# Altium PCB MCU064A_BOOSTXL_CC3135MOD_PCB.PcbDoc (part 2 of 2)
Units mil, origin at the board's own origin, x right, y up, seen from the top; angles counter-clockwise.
Board outline 2300 x 1700 mil, 2 copper layers (Top Layer, Bottom Layer), stack 45.707 mil thick; 110 components, 81 nets, 379 pads, 305 vias.
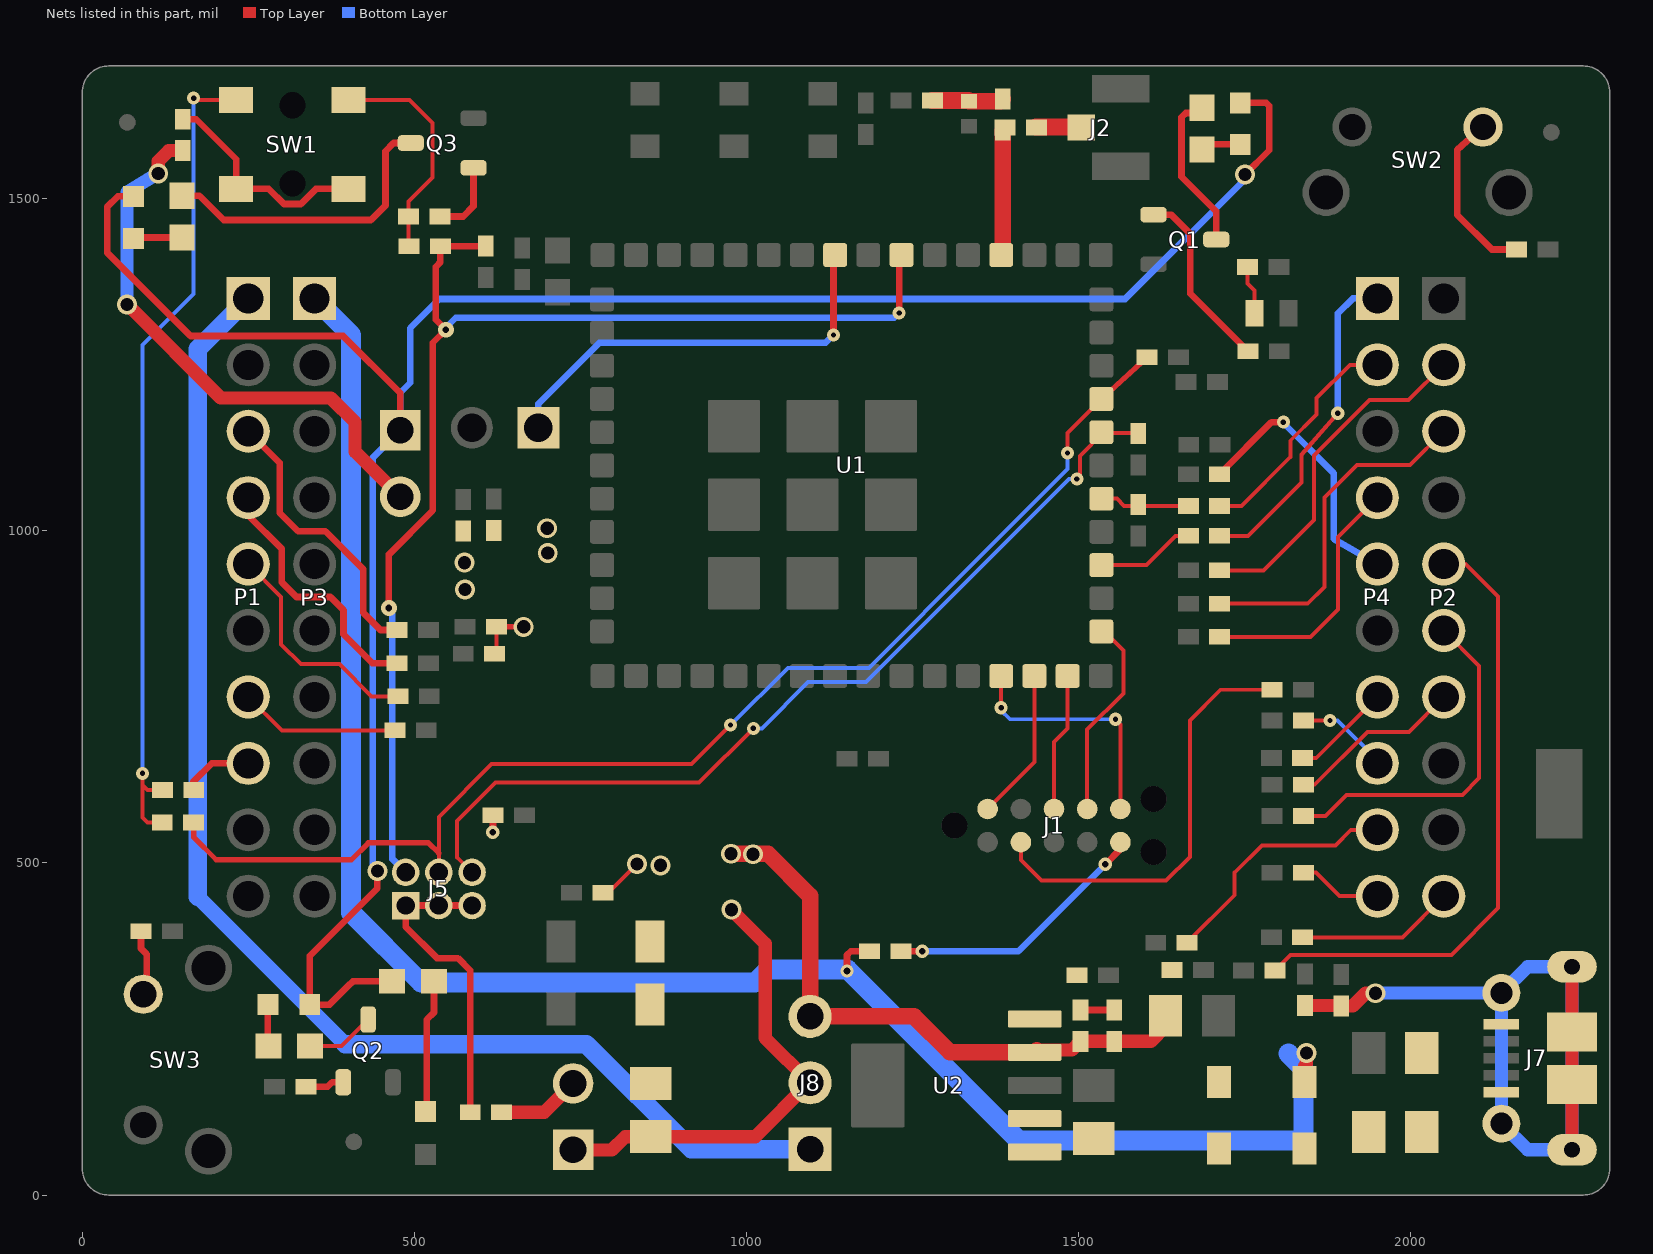
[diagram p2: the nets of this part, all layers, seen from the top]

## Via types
v1: diameter 19.68, hole 7.87, Top Layer to Bottom Layer, tented both sides, 240 vias
v2: diameter 19.68, hole 7.87, Top Layer to Bottom Layer, 40 vias
v3: diameter 30, hole 20, Top Layer to Bottom Layer, tented both sides, 19 vias
v4: diameter 20, hole 10, Top Layer to Bottom Layer, tented both sides, 4 vias
v5: diameter 24, hole 10, Top Layer to Bottom Layer, tented both sides, 2 vias

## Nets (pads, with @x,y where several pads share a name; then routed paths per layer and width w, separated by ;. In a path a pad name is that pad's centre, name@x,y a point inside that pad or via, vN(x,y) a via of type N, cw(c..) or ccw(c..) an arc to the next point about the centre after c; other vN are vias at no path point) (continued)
NetC4_1: C4.1 J2.1 | length 68
  Top Layer w25: J2.1@1502.86,1608.3 J2.1@1503.86,1607.3
  Top Layer w25.4: C4.1@1436.32,1608.3 J2.1@1502.86,1608.3
NetC5_2: C5.2 C7.2 L1.1 | length 107.7
  Top Layer w25.4: C7.2@1280.24,1647.9 1334.3,1647.9 L1.1@1335.3,1646.9 1382.4,1646.9 C5.2@1386,1650.5
NetC8_2: C8.2 R36.1 R37.2 U2.5 | length 51
  Top Layer w10: R36.1@1503,278.62 C8.2@1554,278.62
NetC14_1: C14.1 J7.6 J7.7 J7.8 J7.9 J7.10 J7.11 R38.1 | length 1295.1
  Top Layer w20: R38.1@1841,285.38 C14.1@1893.87,285.38 ; C14.1@1895.8,284.68 1912.98,284.68 1932.2,303.9 v3(1947.2,303.9) ; J7.6@2243.08,68.2 J7.7@2243.08,166.63 J7.8@2243.08,245.37 J7.9@2243.08,343.8
  Bottom Layer w20: v3(1947.2,303.9) J7.10@2136.78,304.43 ; J7.10@2136.78,304.43 2176.15,343.8 J7.9@2243.08,343.8 J7.6@2243.08,68.2 2176.15,68.2 J7.11@2136.78,107.57 J7.10@2136.78,304.43
NetD1_1: D1.1 R44.2 | length 57.2
  Top Layer w10: R44.2@1685.9,1581.98 D1.1@1743.13,1581.98
NetD2_1: D2.1 R41.1 | length 73.9
  Top Layer w6: R41.1@1754.76,1397.3 1754.76,1372.34 1764.92,1362.18 D2.1@1764.92,1327.6
NetD4_2: D4.2 L4.2
NetD5_2: D5.2 R42.1 | length 201.2
  Top Layer w10: D5.2@516.6,125.98 518.8,128.18 518.8,264.1 529.6,274.9 R42.1@529.6,321.8
NetD6_1: D6.1 R45.2 | length 62.8
  Top Layer w10: D6.1@279.6,286.8 279.6,224.88 R45.2@280.25,224.23
NetD7_1: D7.1 R40.2 | length 73.3
  Top Layer w10: D7.1@77.5,1440.5 78.7,1441.7 R40.2@150.3,1441.7
NetJ1_2: J1.2 R1.1 | length 657.2
  Top Layer w6: J1.2@1413.2,531.3 1413.2,504.7 1444.4,473.5 1631.9,473.5 1667.7,509.3 1667.7,714.8 1713.7,760.8 R1.1@1791.48,760.8
NetJ1_5: J1.5 R2.2 | length 404.1
  Top Layer w10: R2.2@1232.62,367.2 v4(1264.9,367.2) ; v4(1540.3,497.9) 1563.2,520.8 J1.5@1563.2,530.7
  Bottom Layer w10: v4(1264.9,367.2) 1409.6,367.2 v4(1540.3,497.9)
NetJ4_1: J4.1 U1.36 | length 649.2
  Top Layer w10: v1(1131.2,1295.1) 1131.2,1416.33 U1.36@1134.3,1419.43
  Bottom Layer w10: J4.1@686.8,1155.2 686.8,1191.37 778.63,1283.2 1119.3,1283.2 v1(1131.2,1295.1)
NetJ5_1: J5.1 J5.3 J5.5 R7.2 | length 469.7
  Top Layer w10: R7.2@584.28,124.9 584.28,205.72 584.28,236.12 584.28,338.22 565.7,356.8 534.2,356.8 487,404 J5.1@487,435.9 J5.3@537,435.9 J5.5@587,435.9
NetJ5_2: J5.2 R8.1 R13.1 U1.34 | length 1850.9
  Top Layer w10: v5(461.8,883.9) 461.8,964.7 527.9,1030.8 527.9,1283.2 v5(547.5,1302.8) 532.2,1318.1 532.2,1397.56 539.32,1404.68 R8.1@539.32,1428.6 539.44,1428.72 R13.1@607.7,1428.72 ; v1(1230.1,1328.2) 1230.1,1413.43 U1.34@1233.8,1417.13
  Bottom Layer w10: v5(461.8,883.9) 467,873.67 467,505.9 J5.2@487,485.9 ; v5(547.5,1302.8) 547.5,1305.96 562.34,1320.8 1222.7,1320.8 v1(1230.1,1328.2)
NetJ5_4: J5.4 R9.1 R12.1 U1.24 | length 1903.5
  Top Layer w6: J5.4@537,485.9 537,569.4 616.6,649 917.5,649 v1(976.3,707.8) ; v1(1483.5,1117.3) 1483.5,1147.42 U1.24@1534.58,1198.5
  Top Layer w8: R9.1@167.82,561 167.82,538.88 201.9,504.8 405.3,504.8 430.8,530.3 521.5,530.3 537,514.8 ; U1.24@1534.58,1198.5 U1.24@1538.96,1202.5 ; U1.24@1535.28,1202.5 U1.24@1538.96,1202.5 ; U1.24@1544,1202.5 U1.24@1538.96,1202.5 ; R12.1@1603.18,1261.2 U1.24@1538.96,1202.5
  Bottom Layer w6: v1@972.2,703.7 v1(976.3,707.8) 1062.4,793.9 1184.38,793.9 1351.18,960.69 1351.32,960.69 1483.5,1092.87 v1(1483.5,1117.3)
NetJ5_6: J5.6 R11.1 U1.23 | length 1376.3
  Top Layer w6: J5.6@581.6,491.3 J5.6@587,485.9 564.3,508.6 564.3,563.2 622.3,621.2 929,621.2 v1(1010.5,702.7) ; v1(1497.5,1078.1) 1502.34,1082.94 1502.34,1112.94 1537.9,1148.5 U1.23@1534.58,1148.5 ; U1.23@1538.8,1147.6 R11.1@1583.82,1147.6
  Bottom Layer w6: v1(1010.5,702.7) 1023.3,702.7 1093,772.4 1180,772.4 1485.7,1078.1 v1(1497.5,1078.1)
NetJ7_1: J7.1 L4.1
NetJ7_5: J7.5 L5.2
NetP1_3: P1.3 R20.2 | length 438.4
  Top Layer w10: P1.3@257.6,1150 P1.3@250,1150 297.3,1102.7 297.3,1027.2 325.1,999.4 366.1,999.4 423.4,942.1 423.4,876.6 449.2,850.8 R20.2@474.28,850.8
NetP1_4: P1.4 R22.2 | length 393.8
  Top Layer w10: P1.4@250,1050 250,1023.4 300.6,972.8 300.6,922.5 322.6,900.5 373.7,900.5 393.48,880.72 393.48,844.42 437.1,800.8 R22.2@474.28,800.8
NetP1_5: P1.5 R25.2 | length 349.5
  Top Layer w6: P1.5@250,950 299.6,900.4 299.6,829.28 329.58,799.3 387.2,799.3 435.7,750.8 R25.2@475.28,750.8
NetP1_7: P1.7 R29.2 | length 241.4
  Top Layer w6: P1.7@250,750 300.7,699.3 R29.2@470.38,699.3
NetP1_8: P1.8 R31.2 | length 107
  Top Layer w10: R31.2@168,610 167,611 167,621.9 195.1,650 P1.8@250,650
NetP2_2: P2.2 R18.1 | length 522.4
  Top Layer w6: R18.1@1712.62,940.5 1778.6,940.5 1854.3,1016.2 1854.3,1113.2 1938.1,1197 1997,1197 P2.2@2050,1250
NetP2_3: P2.3 R19.1 | length 523.7
  Top Layer w6: R19.1@1712.62,890.5 1845.2,890.5 1870.3,915.6 1870.3,1050.2 1919.6,1099.5 1999.5,1099.5 P2.3@2050,1150
NetP2_5: P2.5 R24.1 | length 946.5
  Top Layer w6: R24.1@1795.62,338 1819.32,361.7 2061.6,361.7 2131.9,432 2131.9,901.1 2083,950 P2.5@2050,950
NetP2_6: P2.6 R26.1 | length 534.3
  Top Layer w6: R26.1@1837.1,570.7 1872.1,570.7 1903.9,602.5 2078.2,602.5 2103.4,627.7 2103.4,796.6 P2.6@2050,850
NetP2_7: P2.7 R28.1 | length 267
  Top Layer w6: R28.1@1837.71,617.8 1855.3,617.8 1934.9,697.4 1997.4,697.4 P2.7@2050,750
NetP2_10: P2.10 R34.1 | length 238.1
  Top Layer w6: R34.1@1837.62,388 1988,388 P2.10@2050,450
NetP4_1: P4.1 R16.2 | length 500.4
  Top Layer w6: R16.2@1712.62,992.5 1755.5,992.5 1835.5,1072.5 1835.5,1114.12 v1(1890.4,1177.1)
  Bottom Layer w10: v1(1890.4,1177.1) 1890.4,1327.3 1913.1,1350 P4.1@1950,1350
NetP4_2: P4.2 R17.2 | length 354.3
  Top Layer w6: R17.2@1712.62,1037.5 1745.5,1037.5 1818.9,1110.9 1818.9,1135.7 1858.65,1175.45 1858.65,1200.05 1908.6,1250 P4.2@1950,1250
NetP4_4: P4.4 R21.2 | length 388.1
  Top Layer w6: R21.2@1712.62,840.5 1849.7,840.5 1890.6,881.4 1890.6,990.6 P4.4@1950,1050
NetP4_5: P4.5 R23.2 | length 413.7
  Top Layer w10: R23.2@1712.62,1085.5 1790.82,1163.7 v1(1808.5,1163.7)
  Bottom Layer w10: v1@1806.1,1165 1884.1,1087 1884.1,987.98 P4.5@1950,950
NetP4_7: P4.7 R27.2 | length 150.5
  Top Layer w6: R27.2@1837.62,658 1858,658 P4.7@1950,750
NetP4_8: P4.8 R30.2 | length 153.9
  Top Layer w6: R30.2@1838.72,714.5 v1(1878.8,714.5)
  Top Layer w10: P4.8@1950,636.9 P4.8@1950,650
  Bottom Layer w6: v1(1878.8,714.5) 1890.3,714.5 1950,654.8 P4.8@1950,650
NetP4_9: P4.9 R32.2 | length 376.6
  Top Layer w6: R32.2@1663.62,380 1735.3,451.68 1735.3,485.5 1776.3,526.5 1887,526.5 1910.5,550 P4.9@1950,550
NetP4_10: P4.10 R33.2 | length 125.9
  Top Layer w6: R33.2@1838.72,485.4 1857.8,485.4 1893.2,450 P4.10@1950,450
NetQ1_1: Q1.1 R46.2 | length 280
  Top Layer w10: Q1.1@1612.96,1476.1 1639.3,1476.1 1668.5,1446.9 1668.5,1356.98 R46.2@1755.08,1270.4
NetQ1_3: Q1.3 R44.1 | length 239
  Top Layer w10: R44.1@1685.9,1629.22 1661.72,1629.22 1655.2,1622.7 1655.2,1533.3 1707.44,1481.06 Q1.3@1707.44,1438.7
NetQ2_1: Q2.1 R47.2 | length 59.1
  Top Layer w10: R47.2@336.82,163 369.5,163 376.36,169.86 Q2.1@393.1,169.86
NetQ2_3: Q2.3 R45.1 | length 103.9
  Top Layer w6: R45.1@343.25,224.23 390.39,224.23 Q2.3@430.5,264.34
NetQ3_1: Q3.1 R43.2 | length 114.6
  Top Layer w10: R43.2@538.72,1473.4 573.7,1473.4 589.24,1488.94 Q3.1@589.24,1546.6
NetQ3_3: Q3.3 R40.1 | length 455.6
  Top Layer w10: R40.1@150.3,1504.7 176.4,1504.7 213.1,1468 434.7,1468 456.6,1489.9 456.6,1571.7 468.9,1584 Q3.3@494.76,1584
NetR39_1: R39.1 SW1.1 SW1.2 | length 338.2
  Top Layer w10: R39.1@151.4,1619.82 171.68,1619.82 231.85,1559.65 SW1.1@231.85,1514.97 280.98,1514.97 303.79,1492.16 329.21,1492.16 352.02,1514.97 SW1.2@401.15,1514.97
NetR48_2: R48.2 SW3.1 | length 100.5
  Top Layer w10: R48.2@88.58,397.2 88.58,371.12 96.99,362.71 96.99,307.42 SW3.1@91.86,302.29
NetR49_2: R49.2 SW2.1 | length 260.9
  Top Layer w10: SW2.1@2108.97,1607.91 2070.1,1573.8 2070.1,1476 2122.44,1423.66 R49.2@2159.83,1423.66
RF_BG: C4.2 C5.1 U1.31 | length 184.9
  Top Layer w6: U1.31@1383.88,1419.85 U1.31@1383.94,1419.92
  Top Layer w10: U1.31@1383.88,1419.85 U1.31@1384.3,1419.43
  Top Layer w25.4: U1.31@1383.94,1419.92 1386,1421.97 C5.1@1386,1603.25
SFL_CLK: J1.8 U1.15 | length 208.7
  Top Layer w6: J1.8@1463.2,581.3 1463.2,682.1 1483.6,702.5 U1.15@1483.6,781.57
SFL_CS: J1.10 U1.14 | length 230.4
  Top Layer w6: J1.10@1363.2,581.3 1433.6,651.7 U1.14@1433.6,781.57
  Top Layer w10: U1.14@1433.6,781.57 U1.14@1434.3,780.87
SFL_MISO: J1.6 U1.13 | length 370.3
  Top Layer w6: v1(1383.6,733.7) U1.13@1383.6,781.57 ; v1(1555.6,716.4) 1563.2,708.8 J1.6@1563.2,581.3
  Top Layer w10: J1.6@1563.2,580.7 J1.6@1563.2,581.3
  Bottom Layer w6: v1(1383.6,733.7) 1383.6,729.9 1397.1,716.4 v1(1555.6,716.4)
  Bottom Layer w10: v1@1381.7,734.3 1382.3,733.7 v1(1383.6,733.7)
SFL_MOSI: J1.7 U1.17 | length 311.9
  Top Layer w6: J1.7@1513.2,581.3 1513.2,700.8 1567.7,755.3 1567.7,820.08 1539.28,848.5 U1.17@1534.58,848.5
  Top Layer w10: U1.17@1535.28,852.5 U1.17@1539.28,848.5
SOP_00: R8.2 R43.1 SW1.3 | length 341.3
  Top Layer w6: SW1.3@401.15,1648.83 492.77,1648.83 527.4,1614.2 527.4,1532 507,1511.6 491.48,1496.08 R43.1@491.48,1473.4 491.48,1429.2 R8.2@492.08,1428.6
SOP_01: R9.2 R31.1 SW1.4 | length 1247.8
  Top Layer w6: v1(90.8,635) 90.8,617.8 ; R9.2@120.58,561 98.1,561 90.8,568.3 90.8,617.8 ; R31.1@120.76,610 98.6,610 90.8,617.8 ; v1@167.77,1648.83 SW1.4@231.85,1648.83 ; v1@167.8,1648.86 v1(167.8,1651.5)
  Bottom Layer w6: v1(90.8,635) 90.8,1279.7 167.8,1356.7 v1(167.8,1651.5)
TEST_29: R16.1 U1.19 | length 149
  Top Layer w6: U1.19@1534.58,948.5 1602.3,948.5 1646.3,992.5 R16.1@1665.38,992.5
TEST_30: R14.2 R17.1 U1.21 | length 140.2
  Top Layer w6: U1.21@1534.58,1048.5 1557.86,1048.5 1568.86,1037.5 R14.2@1592.8,1037.5 ; R14.2@1589.4,1040.9 R14.2@1592.8,1037.5 ; R17.1@1665.38,1037.5 R14.2@1592.8,1037.5
VBAT_CC: C1.1 C11.1 C12.1 J6.2 L2.2 R5.1 R6.1 R7.1 R35.2 | length 287.9
  Top Layer w6: R6.1@620.92,814.9 623.62,817.6 R5.1@623.62,855.7 ; v3@664.7,845 v3(664.7,855.6) ; C1.1@783.82,455.3 792.1,455.3 v3(835.3,498.5)
  Top Layer w8: R5.1@623.62,855.7 655.4,855.7 655.5,855.6 v3(664.7,855.6)
  Top Layer w10: C11.1@845.09,382 C11.1@845.6,382.51
  Top Layer w20: R7.1@632.72,124.7 695.7,124.7 J6.2@739,168
  other v3: 870.8,496.4 576.2,911.8 575.5,952.1
VCC_BRD: J3.2 J6.1 J8.2 R15.2 R35.1 R39.2 | length 1588
  Top Layer w6: v4(618,546.1) v4@618.58,546.68 ; R15.2@618,571.12 R15.2@618.58,571.7
  Top Layer w10: v4@618.58,546.68 R15.2@618.58,571.7
  Top Layer w20: v3(67.5,1341) 208.4,1200.1 374.4,1200.1 410.8,1163.7 410.8,1119.3 J3.2@478.8,1051.3 ; v3(114.5,1538.2) 114.5,1556.6 130.48,1572.58 R39.2@151.4,1572.58 ; J6.1@739,68 797.7,68 817.7,88 R35.1@856,88 1013.27,88 1094.27,169 J8.2@1096,169 1028.6,236.4 1028.6,378.6 v3(977.5,429.7)
  Bottom Layer w20: v3(67.5,1341) 67.5,1509.9 v3(114.5,1538.2) ; v3@974.54,433.11 v3@981.46,426.22
VCC_BRD_5V: C13.1 D3.1 D4.1 U2.1 U2.2
VCC_LDO_3V3: C8.1 C9.1 C10.1 J8.3 L3.2 R36.2 U2.4 | length 917
  Top Layer w20: U2.4@1437.41,218.3 1489.92,218.3 R36.2@1503,231.38 C8.1@1554,231.38 1609.28,231.38 1631,253.1 C9.1@1631,270
  Top Layer w25: v3(976.8,513.9) 1032.5,513.9 1096,450.4 J8.3@1096,269 1252.5,269 1306.5,215 U2.4@1434.11,215 U2.4@1437.41,218.3
  other v3: 1010,513.1 701,966.7 700.1,1004
VCC_LED: D1.2 D6.2 D7.2 J3.1 R42.2 | length 3455.1
  Top Layer w6: D6.2@342.6,286.8 D6.2@342.6,293.03
  Top Layer w10: D7.2@77.5,1503.5 77.4,1503.6 53.6,1503.6 37.6,1487.6 37.6,1419.1 163.22,1293.48 392.82,1293.48 478.8,1207.5 J3.1@478.8,1151.3 ; v3(444.5,488) 444.5,461.9 342.6,360 D6.2@342.6,286.8 372.5,286.8 401.1,315.4 407.5,321.8 R42.2@466.6,321.8 ; D1.2@1743.6,1644.5 1782.6,1644.5 1787.2,1639.9 1787.2,1573.2 v3(1750.7,1536.7)
  Bottom Layer w10: v3(444.5,488) 440.4,488 437.29,491.11 437.29,1109.79 J3.1@478.8,1151.3 478.8,1208 493.9,1223.1 493.9,1305.3 537.64,1349.04 1570.27,1349.04 1750.7,1529.48 v3(1750.7,1536.7)
VCC_MCU_3V3: J8.1 P1.1 | length 2011.9
  Bottom Layer w23: 173.9,449.2 395.9,227.2
  Bottom Layer w28: 173.9,449.2 173.9,1273.9 P1.1@250,1350 ; 395.9,227.2 759.1,227.2 917.3,69 J8.1@1096,69
VCC_MCU_5V: D3.2 P3.1 R2.1 | length 2782.4
  Top Layer w10: v4(1151.4,337.3) 1151.4,361.51 1157.09,367.2 R2.1@1185.38,367.2
  Top Layer w19.68: D3.2@1840.47,170 1840.47,194.43 1843.4,197.36 v3(1843.4,213.9)
  Bottom Layer w30: P3.1@350,1350 405,1295 405,425 510,320 1013.13,320 1032.93,339.8 1152.27,339.8 1410.07,82 1832.6,82 1838.6,88 1838.6,190.4 1816,213
pads on no net: E1.3 E1.4 E1.5 E1.6 FID1.1 FID2.1 FID3.1 FID4.1 FID5.1 FID6.1 J1.3 J1.4 J1.MH1 J1.MH2 J1.MH3 J2.2@1563.9,1666.36 J2.3@1563.9,1548.24 J7.2 J7.3 J7.4 P1.2 P1.6 P1.9 P1.10 P2.4 P2.8 P2.9 P3.3 P3.4 P3.5 P3.6 P3.7 P3.8 P3.9 P3.10 P4.3 P4.6 SW1.MH1 SW1.MH2 SW2.MH1 SW2.MH2 SW3.MH1 SW3.MH2 U1.3 U1.9 U1.10 U1.12 U1.18 U1.20 U1.22 U1.33 U1.39 U1.41 U1.42 U1.45 U1.53 U1.54 U1.55@1003.09,899.68 U1.55@1003.09,942.99 U1.56@1077.89,899.68 U1.56@1077.89,942.99 U1.56@1121.2,899.68 U1.56@1121.2,942.99 U1.57@1196,899.68 U1.57@1196,942.99 U1.57@1239.31,899.68 U1.57@1239.31,942.99 U1.58@959.78,1017.79 U1.58@959.78,1061.1 U1.58@1003.09,1017.79 U1.58@1003.09,1061.1 U1.59@1077.89,1017.79 U1.59@1077.89,1061.1 U1.59@1121.2,1017.79 U1.59@1121.2,1061.1 U1.60@1196,1017.79 U1.60@1196,1061.1 U1.60@1239.31,1017.79 U1.60@1239.31,1061.1 U1.61@959.78,1135.9 U1.61@959.78,1179.21 U1.61@1003.09,1135.9 U1.61@1003.09,1179.21 U1.62@1077.89,1135.9 U1.62@1077.89,1179.21 U1.62@1121.2,1135.9 U1.62@1121.2,1179.21 U1.63@1196,1135.9 U1.63@1196,1179.21 U1.63@1239.31,1135.9 U1.63@1239.31,1179.21 U2.6@1175.84,135.28 U2.6@1175.84,194.72 U2.6@1219.94,135.28 U2.6@1219.94,194.72

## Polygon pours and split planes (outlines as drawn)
GND on Top Layer "GND_L01_P121" (solid, remove dead copper, pour order 121): -10,1658.1 -10,1675.5 11.7,1697.2 2268,1697.2 2268,1692.7 2285.3,1675.4 2289.7,1671 2289.7,19.1 2289.7,1.7 2281,-7 2276.6,-2.6 11.7,-2.6 -10,19.1
NetC2_1 on Top Layer "NETC2_1_L01_P096" (solid, remove dead copper, pour order 96): 644.33,1395.7 739.78,1395.7 761.9,1395.7 771.2,1386.4 704.46,1293.04 661.2,1219.67 649.13,1199.2 649.13,1186.07 642.55,1038.15 633.7,1029.3 545.7,1029.3 544,1219.67
VBAT_CC on Top Layer "VBAT_CC_L01_P094" (solid, remove dead copper, pour order 94): 602.79,1024.17 532.87,1024.17 532.5,1023.8 529.5,1020.8 529.51,914.29 529.51,889.3 598.1,889.3 603.5,894.7 602.79,959.8
VCC_LDO_3V3 on Top Layer "VCC_LDO_3V3_L01_P092" (solid, remove dead copper, pour order 92): 602.79,1022.29 730.38,1022.3 730.38,960.02 710.25,939.7 602.6,939.7
VBAT_CC on Top Layer "TOP-GND" (solid, remove dead copper, pour order 38): 701.94,231 743,231 763.7,241.9 763.7,469.4 815.2,520.9 884.2,520.9 940.9,464.2 940.9,166.8 894.88,120.77 711.13,120.77 680.17,151.73 680.17,209.23
GND on Top Layer "Top Layer-GND" (solid, remove dead copper, pour order 33): 1690,235 1770,235 1821.87,235 1821.87,315 1690,315 1685,310 1685,238 1687,236 1688,235 1691,235
VCC_LDO_3V3 on Top Layer "Top Layer-VCC_LDO_3V3" (solid, remove dead copper, pour order 36): 1382,225 1382,205 1387,200 1482,200 1492,210 1562,210 1577,225 1657,225 1662,230 1662,345 1652,355 1577,355 1572,350 1572,255 1567,250 1492,250 1486,244 1477,235 1459,235 1387,235 1382,230 1382,224
NetC8_2 on Top Layer "Top Layer-NetC29_2" (solid, remove dead copper, pour order 35): 1388.46,251.82 1478.11,251.82 1483.68,257.39 1486.48,260.19 1494.84,260.19 1561.19,260.19 1565,264 1565,298 1559,304 1522,304 1516.31,309.69 1513.88,312.12 1513.88,333.1 1513.88,347.85 1511.81,349.92 1409.58,349.92 1394.94,335.28 1384.38,324.72 1384.38,273.35 1384.38,254.74 1386.97,252.15
GND on Top Layer "TOP-GND" (solid, pour order 34): 428 vertices, not listed, extent 1927.21,1050.03 2099,1419
VCC_BRD_5V on Top Layer "TOP-VCC_BRD_5V" (solid, pour order 37): 1376,55 1376,125 1386,135 1478,135 1488.01,125 1567.99,124.99 1592,149 1592,186.8 1610.2,205 1721.66,205 1738.46,188.2 1738.46,39.08 1719.38,20 1596,20 1571,45 1386,45
NetJ7_1 on Top Layer "Top Layer-NetJ7_1" (solid, remove dead copper, pour order 31): 1989.09,64.08 1989.09,128.09 2025,164 2026,165 2053,165 2162.3,165 2163.65,163.65 2163.65,146.44 2162.21,145 2087.51,145 2074.27,131.75 2074.27,60.27 2067,53 2000.17,53
NetJ7_5 on Top Layer "Top Layer-NetJ7_5" (solid, remove dead copper, pour order 30): 1991.25,246.86 2014.39,270 2159.31,270 2164.38,264.92 2164.38,249.41 2162.12,247.14 2099.9,247.14 2076.57,223.81 2076.57,185.57 2064,173 2001.29,173 1991.25,183.04
NetD4_2 on Top Layer "Top Layer-NetD4_2" (solid, remove dead copper, pour order 32): 1821.43,45.07 1827.52,38.99 1946.16,38.99 1963.54,56.37 1963.54,126.33 1958.88,130.99 1901.5,130.99 1894.5,123.99 1869.5,98.99 1856.5,98.99 1825.76,98.99 1821.43,94.66
GND on Bottom Layer "GND_L02_P100" (solid, remove dead copper, pour order 100): -1.1,1661.9 21.4,1684.4 21.4,1691.8 2250.5,1691.8 2272.9,1714.2 2299,1688.1 2299,1676.8 2299,38.8 2302.8,35 2276.6,8.8 2276.6,-9.9 13.9,-9.9 6.4,-17.4 -12.3,1.3 -12.3,20
VBAT_CC on Bottom Layer "VBAT_CC_L02_P084" (solid, remove dead copper, pour order 84): 667.9,986.9 556.1,983.4 584.8,752.98 592.94,656.98 797.1,470.9 895.5,470.9 895.5,500.6 728.1,699.6 690.5,875 674.87,947.89
VCC_LDO_3V3 on Bottom Layer "VCC_LDO_3V3_L02_P082" (solid, remove dead copper, pour order 82): 915.65,500.96 732.3,684.31 674.6,959.2 670.4,1034.1 671.72,1035.42 730.2,1035.42 730.2,1034.1 732.3,1032 783.6,973.57 792.5,700.3 892.3,612.2 1073.3,495.2
VCC_LED on Bottom Layer "Bottom Layer-No Net 2" (solid, remove dead copper, pour order 64): 517.2,1107.1 425.4,1107.1 406.3,1126.2 419.9,1309.45 486.85,1309.45 516.5,1288.3 517.2,1287.6
VCC_MCU_5V on Bottom Layer "Bottom Layer-No Net" (solid, remove dead copper, pour order 58): 1246.02,245.05 1907.71,236.06 1936,147 1900.04,58.4 1619.9,58.4 1327.56,58.4
VCC_MCU_3V3 on Bottom Layer "Bottom Layer-No Net 1" (solid, remove dead copper, pour order 60): 778.1,33.9 1136.8,33.9 1136.8,99.9 1037.3,99.9 947.9,142.2 778.1,235.94
VCC_BRD on Bottom Layer "Bottom Layer-No Net 3" (solid, remove dead copper, pour order 66): 449,1080.6 565.13,1080.6 623.21,624.44 648.48,606.92 794.4,461 996,461 996,430 996,418.6 945.4,418.6 836.8,418.6 758.8,418.6 477.85,517.85 447,1080
no net on Keep-Out Layer "Keep-Out Layer-No Net" (solid, remove dead copper): 812,1693.1 812,1631.4 812.6,1630.8 794.1,1630.8 794.1,1619.7 792.5,1618.1 795.1,1615.5 896,1615.5 896,1693.1
no net on Keep-Out Layer "Keep-Out Layer-No Net" (solid, remove dead copper): 793,1489.8 794,1490.8 1024.4,1490.8 1024.4,1629.7 1021.7,1632.4 1021.2,1632.9 896,1632.9 896,1619.2 896,1615.5 899.7,1615.5 792.5,1615.5

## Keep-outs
Top Layer:
  circle w0: c1872.75,1509.49 r45
  circle w0: c2148.34,1509.49 r45
  circle w0: c190.28,341.66 r45
  circle w0: c190.28,66.07 r45
Bottom Layer:
  circle w0: c316.5,1522.84 r23
  circle w0: c316.5,1640.96 r23
  circle w0: c190.28,66.07 r45
  circle w0: c1872.55,1509.38 r45
  circle w0: c2148.44,1509.88 r45
  circle w0: c190.28,341.66 r45
Keep-Out Layer:
  lines w10: 10,1700 2260,1700 cw(c2260,1660) 2300,1660 2300,40 cw(c2260,40) 2260,0 40,0 cw(c40,40) 0,40 0,1660 cw(c40,1660) 40,1700
  text ".Layer_Name" at 727,-858.49 h60

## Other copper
Top Layer:
  pour cut-out: 1168,1612.4
  pour cut-out: 1168.1,1665.8 1249.3,1665.8 1274.5,1665.8 1273,1628.1 1258.3,1628.1 1191.9,1628.1 1191.9,1613.4 1190.1,1611.6 1168.1,1612.4
  pour cut-out: 787.98,1688.6 1168,1688.6 1168,1495.8 1074,1495.8 788.3,1495.8
  pour cut-out: 367.1,808.2 367.1,818.04 393.48,844.42 448.4,789.5 546.2,789.5 546.2,750.8 435.7,750.8
  pour cut-out: 808.47,115.38 820.81,127.71 912.74,127.71 912.74,105.13 902.65,95.04 828.01,95.04 808.15,114.9
  pour cut-out: 2197.55,96.93 2197.55,302.63 2204.97,310.05 2258.54,310.05 2267.53,301.06 2267.53,102.43 2252.67,87.57 2207.99,87.57 2197.52,98.04
  pour cut-out: 287,1313 213,1313 213,1387 287,1387
  pour cut-out: 1859,259 1857,261 1857,264 1862,269 1912,269 1915,266 1915,260 1914,259
  pour cut-out: 1474.94,1574.69 1474.78,1639.6 1532.44,1639.6 1532.54,1574.85
  pour cut-out: 1352.12,1350.59 1352.12,1442.9 1414.08,1442.9 1414.08,1350.67
  text "L01 TOP LAYER" at 727,-858.49 h60
Bottom Layer:
  pour cut-out: 787.98,1688.6 1167.98,1688.6 1167.98,1508.6 1073.98,1508.6 788.28,1508.6
  text "L04 BOTTOM LAYER" at 727,-858.49 h60

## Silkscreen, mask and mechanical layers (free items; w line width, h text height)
Top Overlay:
  drawing of 2694 lines, arcs and shapes, not listed
  text "FRST" at 88.2,1658.9 h30
  text "BOOSTXL-CC3135MOD" at 860.3,1482 h45
  text "RST" at 1730.4,1451.5 h32
  text "P4" at 1929,1417 h30
  text "P2" at 2025,1417 h30
  text "P3" at 329,1393.6 h30
  text "P1" at 189,1392.3 h30
  text "IRQ" at 2121.4,1231.7 h30
  text "VCC_RST" at 594.3,1227.2 h40
  text "CS#" at 2115.1,1145.2 h30
  text "TX" at 130.4,1130.5 h30
  text "RX" at 130.1,1034.6 h30
  text "CTS" at 1826.1,1009.7 h30
  text "RTS" at 1828.9,938.1 h30
  text "RST" at 2122.9,933.5 h30
  text "nHIB" at 77.9,931.1 h30
  text "VCC_LED" at 439.4,900.2 h72.83
  text "MOSI" at 2120.3,838 h30
  text "MISO" at 2086.7,735.7 h30
  text "CLK" at 98.3,735.1 h30
  text "NWP" at 1902,708 h30 r90
  text "FRST" at 77.1,640.3 h30
  text "MAC" at 1905,598 h30 r90
  text "RST*" at 2122.5,436.7 h30
  text "LDO" at 1158,258 h32
  text "VBAT_CC" at 573.8,181.2 h32
  text "PWR" at 558.3,166.3 h30 r90
  text "nHIB" at 243.8,94.2 h30
  text "VCC_BRD" at 570.1,49.6 h32
  text "MCU" at 1156,47 h32
  text "USB PWR" at 1930.68,13.61 h30
  text ".Layer_Name" at 727,-858.49 h60
Bottom Overlay:
  drawing of 3506 lines, arcs and shapes, not listed
  text "For evaluation only;  / not FCC approved for resale." at 1824.3,1476.1 h60
  text "P1" at 286.4,1430.2 h32
  text "1" at 200.4,1425.03 h40
  text "P4" at 2006.17,1421.63 h32
  text "P2" at 2094.71,1422.25 h32
  text "21" at 485.7,1420.4 h40
  text "5V" at 547.6,1342.9 h72.83
  text "40" at 1876.6,1339.9 h40
  text "GND" at 2282.8,1333.1 h72.83
  text "3V3" at 148.9,1326.7 h72.83
  text "GND" at 581.9,1237.4 h72.83
  text "IRQ" at 2207.9,1207.54 h30
  text "TX" at 196.4,1108.1 h30
  text "CS#" at 2214.49,1108.31 h30
  text "CTS" at 1866,1037.8 h30
  text "RX" at 196.4,1009.7 h30
  text "RTS" at 1896,913.88 h30
  text "RST" at 2214.97,910.31 h30
  text "nHIB" at 196.4,906.5 h30
  text "SimpleLink BoosterPack" at 1672.8,825.9 h72.83
  text "MOSI" at 2228.11,809.21 h30
  text "BOOSTXL-CC3135MOD" at 1672.8,768.8 h72.83
  text "NWP" at 1866,732.9 h30
  text "MISO" at 2238.74,707.71 h30
  text "CLK" at 196.4,706.18 h30
  text "FRST" at 196.4,608.18 h30
  text "MAC" at 1896,597.18 h30
  text "RST*" at 2225,410.81 h30
  text "10" at 284.5,336.1 h40
  text "30" at 396.6,318.48 h40
  text "11" at 2091.55,316.83 h40
  text "31" at 1988.55,314.41 h40
  text "Rev A" at 1784.8,207 h40
  text "MCU064" at 1813.9,77.66 h50
  text ".Layer_Name" at 727,-858.49 h60
  text "String" at 1998.3,-1110.9 h72.83
Top Paste:
  text ".Layer_Name" at 727,-858.49 h60
Bottom Paste:
  text ".Layer_Name" at 727,-858.49 h60
Top Solder:
  text ".Layer_Name" at 727,-858.49 h60
  text ".Layer_Name" at 727,-858.49 h60
Bottom Solder:
  text ".Layer_Name" at 727,-858.49 h60
Drill Guide:
  text ".Layer_Name" at 727,-858.49 h60
M1 Board Outline:
  the board outline again, w10
M2 Board Dimensions:
  rectangle: 150,-275 275,-150
  rectangle: 275,-400 650,-275
  lines w1: 2208.99,1759 2210,1760
  lines w7: 150,-275 1150,-275 ; 275,-400 275,-150 ; 400,-400 400,-150 ; 650,-400 650,-150 ; 900,-400 900,-150 ; 150,-400 1150,-400 1150,-150 150,-150 150,-400
  lines w10: -77.03,0.12 -0.85,0.12 ; -19.29,-18.32 -0.85,0.12 ; -19.29,18.57 -0.85,0.12 ; 2291.28,1726.64 2291.28,1691.28 ; 2326.64,1691.28 2291.28,1691.28 ; 2361.99,1762 2291.28,1691.28 ; 2363,1763 2548,1763
  text "R" at 2568,1753 h25
  text "40.00 mil X4" at 2608,1753 h25
  text "(0,0)" at -125.16,-57.16 h25
M3 3D STEP Top:
  text ".Layer_Name" at 727,-858.49 h60
M4 3D STEP Bottom:
  text ".Layer_Name" at 727,-858.49 h60
M5 Assembly Top:
  circle w6: c460.4,344.8 r8
  circle w6: c626.8,1546.6 r8
  circle w6: c1434.88,31.28 r8
  circle w6: c1170.94,24.1 r8
  circle w6: c668.69,24.35 r8
  circle w6: c2088.18,154.32 r8
  rectangle: 1777.62,1664.6 1838.88,1676.98
  rectangle: 199.95,1413.88 217.3,1474.9
  lines w10: -142,-930.17 6458,-930.17 ; -142,-726.83 6460,-726.83 ; -142,-523.5 -142,-1133.5 3863,-1133.5 6460,-1133.5 6460,-523.5 -141.5,-523.5 -141.5,-1133.5 1434,-1133.5 ; 2323,-1133.5 2323,-523.5 ; 3590,-726.83 3590,-523.5 ; 4430,-726.83 4430,-523.5 ; 5052,-1140 5052,-937.17
  text "COMPONENTS MARKED 'DNP' SHOULD NOT BE POPULATED." at 1303.5,-318.5 h60
  text "ASSEMBLY VARIANT:" at 1303,-434 h60
  text ".VariantName" at 2339,-434 h60
  text ".PRJ_Number" at 2863.59,-655.43 h60
  text "PCB VIEWED FROM TOP SIDE" at -78.5,-655.67 h60
  text "BOARD #:" at 2398,-655.67 h60
  text "REV:" at 3788,-655.67 h60
  text ".PCB_Rev" at 4079.5,-655.67 h60
  text "SVN REV:" at 4626,-655.67 h60
  text ".VersionControl_RevNumber" at 5132,-655.67 h60
  text ".Layer_Name" at 741.3,-859.5 h60
  text ".plot_File_Name" at 595.7,-1062.9 h60
  text "PLOT NAME =" at -78.5,-1064.33 h60
  text "GENERATED    :" at 2400,-1064.33 h60
  text ".Print_Date" at 3269.5,-1064.33 h60
  text ".Print_Time" at 3998.5,-1064.33 h60
  text "TEXAS INSTRUMENTS" at 5263,-1064.33 h60
M6 Assembly Bottom:
  lines w10: -142.5,-727.33 6459.5,-727.33 ; -140.5,-930.67 6459.5,-930.67 ; 1265.5,-1140.5 1265.5,-937.67 ; 1887.5,-727.33 1887.5,-524 ; 2727.5,-727.33 2727.5,-524 ; 3994.5,-1134 3994.5,-524 ; 4883.5,-1134 6459,-1134 6459,-524 -142.5,-524 -142.5,-1134 2454.5,-1134 6459.5,-1134 6459.5,-524
  text "COMPONENTS MARKED 'DNP' SHOULD NOT BE POPULATED." at 6252,-318 h60
  text ".VariantName" at 5208,-434 h60
  text "ASSEMBLY VARIANT:" at 6247,-434 h60
  text ".VersionControl_RevNumber" at 1185.5,-656.17 h60
  text "SVN REV:" at 1691.5,-656.17 h60
  text ".PCB_Rev" at 2238,-656.17 h60
  text "REV:" at 2529.5,-656.17 h60
  text ".PRJ_Number" at 3374,-656.17 h60
  text "BOARD #:" at 3919.5,-656.17 h60
  text "PCB VIEWED FROM BOTTOM SIDE" at 6396,-656.17 h60
  text ".Layer_Name" at 731.6,-852.6 h60
  text ".plot_File_Name" at 5736,-1059.7 h60
  text "TEXAS INSTRUMENTS" at 1054.5,-1064.83 h60
  text ".Print_Time" at 2319,-1064.83 h60
  text ".Print_Date" at 3048,-1064.83 h60
  text "GENERATED    :" at 3917.5,-1064.83 h60
  text "PLOT NAME =" at 6396,-1064.83 h60
M9 Title Sheet:
  drawing of 57 lines, arcs and shapes, not listed
  text "1" at 889.84,8036.5 h70
  text "2" at 3385.5,8036.5 h70
  text "3" at 5874.84,8036.5 h70
  text "4" at 8381.51,8036.5 h70
  text "5" at 10880.5,8036.5 h70
  text "6" at 13385.5,8036.5 h70
  text "A" at -266.5,6893.5 h70
  text "A" at 14533.5,6893.5 h70
  text "B" at -266.5,4513.5 h70
  text "B" at 14533.5,4513.5 h70
  text "C" at -266.5,2138.5 h70
  text "C" at 14533.5,2138.5 h70
  text "PROJECT TITLE:" at 11493.5,277.5 h45
  text ".PRJ_Title" at 11543.5,144.17 h70
  text "DESIGNED FOR:" at 11493.5,-23.5 h45
  text ".PRJ_Customer" at 11543.5,-163.5 h70
  text "D" at -266.5,-231.5 h70
  text "D" at 14533.5,-231.5 h70
  text "FILE NAME:" at 11493.5,-323.5 h45
  text ".PCB_File_Name_No_Path" at 11543.5,-443.5 h70
  text "Texas Instruments (TI) and/or its licensors do not warrant the accuracy or completeness of this specification" at 6524,-605.34 h45
  text "ENGINEER:" at 11493.5,-613.5 h45
  text "LAYOUT BY:" at 12998.5,-613.5 h45
  text "or any information contained therein. TI and/or its licensors do not warrant that this design will meet" at 6479.01,-718 h45
  text ".PRJ_Engineer" at 11543.5,-768.49 h70
  text ".PCB_Layout" at 13049,-768.49 h70
  text "the specifications, will be suitable for your application or fit for any particular purpose, or will operate in" at 6479.01,-830.67 h45
  text "ALTIUM DESIGNER VERSION:" at 12998.5,-923.5 h45
  text "an implementation. TI and/or its licensors do not warrant that the design is production worthy. You should" at 6479.01,-943.33 h45
  text "completely validate and test your design implementation to confirm the system functionality for your application." at 6524,-1056 h45
  text ".print_Scale" at 11543.5,-1056.83 h70
  text ".Application_BuildNumber" at 13049,-1056.83 h70
  text "1" at 889.84,-1263.5 h70
  text "2" at 3385.5,-1263.5 h70
  text "3" at 5874.84,-1263.5 h70
  text "4" at 8381.51,-1263.5 h70
  text "5" at 10880.5,-1263.5 h70
  text "6" at 13385.5,-1263.5 h70
M10 Fab Notes:
  drawing of 185 lines, arcs and shapes, not listed
  text "DESIGN INFORMATION" at 12531.02,5910 h60
  text "MIN. TRACK WIDTH:" at 11886.46,5730 h60
  text "6" at 12982.7,5730 h60
  text "MIL" at 13137.46,5730 h60
  text "3" at 12985,5600 h60
  text "MIN. CLEARANCE:" at 11886.46,5598 h60
  text "MIL" at 13137.46,5598 h60
  text "MIN. VIA PAD SIZE:" at 11886.46,5466 h60
  text "MIL" at 13137.46,5466 h60
  text "0.05mm (2MIL)" at 12581.46,5324.29 h60
  text "MINIMUM ANNULAR RING" at 11557.23,5320.01 h60
  text "EXTERNAL" at 13289.46,5320.01 h60
  text "PER" at 11757.23,5202 h60
  text "IPC-D-275 CLASS 2 LEVEL C" at 11977.23,5202 h60
  text "MIL, HOLES" at 13465.46,5089.71 h60
  text "+/-" at 13073,5089 h60
  text "+/-" at 13927,5089 h60
  text "REGISTRATION TOLERANCES:" at 11557.23,5084 h60
  text "METAL" at 12757,5084 h60
  text "5" at 13333.2,5084 h60
  text "3" at 14166.2,5084 h60
  text "MIL" at 14282.46,5084 h60
  text "MATERIAL:" at 11482.46,4874.54 h60
  text "FR-4 High Tg" at 12468.9,4734.21 h60
  text "FR-408" at 11903.46,4725.64 h60
  text "X" at 12315.46,4725.64 h60
  text "OTHER" at 13391.46,4725.64 h60
  text "1.2 mm+/-10%" at 13755,4565 h60
  text "62 MIL (1.6mm) +/-10%" at 12223.56,4562.92 h60
  text "THICKNESS:" at 11557.23,4558.64 h60
  text "X" at 13390.4,4558.64 h60
  text "OTHER" at 13488.46,4558.64 h60
  text "TOLERANCE:" at 11557.23,4400.64 h60
  text "X" at 12396.53,4400.64 h60
  text "ANSI IPC-6012 TYPE 3 CLASS 2" at 12583.48,4400.64 h60
  text "OTHER +/-" at 12583.46,4244.64 h60
  text "BOW & TWIST:" at 11557.23,4087.64 h60
  text "X" at 12396.53,4087.64 h60
  text "ANSI IPC-6012 TYPE 3 CLASS 2" at 12583.48,4087.64 h60
  text "OTHER +/-" at 12583.46,3929.13 h60
  text "DRILLING:" at 11482.46,3790.64 h60
  text "REFERENCE:" at 11557.23,3673.64 h60
  text "X" at 12205.46,3673.64 h60
  text "AS SHOWN" at 12392.46,3673.64 h60
  text "X" at 13106.46,3673.64 h60
  text "NC_DRILL FILES" at 13243.46,3673.64 h60
  text "PTH MIN COPPER THICKNESS:" at 11557.23,3515.64 h60
  text "X" at 12907.46,3515.64 h60
  text "1MIL" at 13044.46,3515.64 h60
  text "OTHER" at 13541.46,3515.64 h60
  text "BOARD FINISH:" at 11482.46,3356.64 h60
  text "SILKSCREEN:" at 11637.68,3238.64 h60
  text "X" at 12586.46,3238.64 h60
  text "TOP" at 12712.46,3238.64 h60
  text "X" at 13096.46,3238.64 h60
  text "BOTTOM" at 13223.46,3238.64 h60
  text "SILKSCREEN COLOR:" at 11637.68,3071.64 h60
  text "X" at 12585.42,3071.64 h60
  text "WHITE" at 12712.46,3071.64 h60
  text "OTHER" at 13223.46,3071.64 h60
  text "SOLDER RESIST COLOR:" at 11637.68,2901.64 h60
  text "X" at 13310.42,2747.44 h60
  text "GREEN" at 12332.46,2742.44 h60
  text "BLUE" at 12923.46,2742.44 h60
  text "OTHER" at 13461.46,2742.44 h60
  text "RED" at 13851.46,2737.44 h60
  text "IMMERSION GOLD (ENIG)" at 12543.46,2553.92 h60
  text "ENEPIG" at 13881,2550.64 h60
  text "SURFACE FINISH:" at 11482.46,2549.64 h60
  text "X" at 12356.51,2549.64 h60
  text "IMM. TIN/SILVER OR EQUIV" at 11812,2392.64 h60
  text "OTHER" at 13243.46,2392.64 h60
  text "ARRAY/PANEL:" at 11482.46,2213.64 h60
  text "CUT AND TRIM PER MECH LAYER 1" at 12543.46,2209.35 h60
  text "N.C. ROUTE" at 12543.46,2057.64 h60
  text "X" at 13222.46,2057.64 h60
  text "V. SCORE" at 13409.46,2057.64 h60
  text "CERTIFICATION:" at 11482.46,1920.64 h60
  text "MATERIALS AND WORKMANSHIP FOR ALL PCBS" at 12207.46,1920.64 h60
  text "TO MEET OR EXCEED THE REQUIREMENTS OF:" at 12207.46,1822.64 h60
  text "X" at 11833.96,1686.14 h60
  text "ANSI IPC-A-600F CLASS ->" at 11972.96,1686.14 h60
  text "X" at 13612.02,1686.14 h60
  text "2" at 13730.96,1686.14 h60
  text "1" at 13415.96,1684.64 h60
  text "3" at 14084.96,1684.64 h60
  text "X" at 11836.02,1526.64 h60
  text "UL 94V-0" at 11972.96,1526.64 h60
  text "X" at 12648.02,1526.64 h60
  text "RoHS" at 12784.96,1526.64 h60
  text "OTHER" at 13429.36,1526.64 h60
  text "PER ORDER" at 13826.42,1526.64 h60
  text "ADDITIONAL REQUIREMENTS:" at 11482.46,1385.64 h60
  text "MICROSECTION:" at 11557.23,1270.64 h60
  text "YES" at 12462.96,1270.64 h60
  text "REQUIRED" at 13324.46,1114.5 h60
  text "BARE BOARD ELEC. TEST:" at 11557.23,1111.64 h60
  text "NONE" at 12862.96,1111.64 h60
  text "X" at 13197.46,1111.64 h60
  text "PER ORDER" at 13916.46,1111.64 h60
  text "MANUFACTURER'S UL:" at 11557.23,954.64 h60
  text "RAIL" at 12722.96,950.35 h60
  text "METAL" at 13214.77,950.35 h60
  text "X" at 13590,950 h60
  text "SILK" at 13726.46,950.35 h60
M11 Gerber Information:
  lines w10: -142,-930.17 6458,-930.17 ; -142,-726.83 6460,-726.83 ; -142,-523.5 -142,-1133.5 3863,-1133.5 6460,-1133.5 6460,-523.5 -141.5,-523.5 -141.5,-1133.5 1434,-1133.5 ; 2323,-1133.5 2323,-523.5 ; 3590,-726.83 3590,-523.5 ; 4430,-726.83 4430,-523.5 ; 5052,-1140 5052,-937.17
  text "ALL ARTWORK VIEWED FROM TOP SIDE" at -78.5,-655.67 h60
  text "BOARD #:" at 2398,-655.67 h60
  text ".PRJ_Number" at 2943.5,-655.67 h60
  text "REV:" at 3788,-655.67 h60
  text ".PCB_Rev" at 4079.5,-655.67 h60
  text "SVN REV:" at 4626,-655.67 h60
  text ".VersionControl_RevNumber" at 5132,-655.67 h60
  text "LAYER NAME =" at -78.5,-858.49 h60
  text ".plot_File_Name" at 610,-1050 h60
  text "PLOT NAME =" at -78.5,-1064.33 h60
  text "GENERATED    :" at 2400,-1064.33 h60
  text ".Print_Date" at 3269.5,-1064.33 h60
  text ".Print_Time" at 3998.5,-1064.33 h60
  text "TEXAS INSTRUMENTS" at 5263,-1064.33 h60
M12 Stackup:
  drawing of 238 lines, arcs and shapes, not listed
  text "CONTROLLED IMPEDANCE USING CPW with GND" at 3984.4,4418.93 h70
  text "GAP" at 5505.9,4072.27 h70
  text "REFERENCE GND" at 9345.9,4062.27 h70
  text "IMPEDANCE +/- 10%" at 6839.4,4048.93 h70
  text "L2" at 9785.9,3772.27 h70
  text "6.5 mil" at 5356.4,3763.93 h70
  text "50 OHMS" at 7589.4,3763.93 h70
  text "W" at 2075.9,3379.27 h70
  text "Layer" at 3693.5,3350.7 h60
  text "Name" at 4103.41,3350.7 h60
  text "Material" at 5033.15,3350.7 h60
  text "Thickness" at 5892.92,3350.7 h60
  text "Constant" at 6542.76,3350.7 h60
  text "Board Layer Stack" at 7112.62,3350.7 h60
  text "L1" at 2970.9,3249.27 h70
  text "1" at 3693.5,3230.7 h60
  text "Top Overlay" at 4103.41,3230.7 h60
  text "2" at 3693.5,3110.7 h60
  text "Top Solder" at 4103.41,3110.7 h60
  text "Solder Resist" at 5033.15,3110.7 h60
  text "0.60mil" at 5892.92,3110.7 h60
  text "3.5" at 6542.76,3110.7 h60
  text "G" at 2355.9,3109.27 h70
  text "H" at 1930.9,3084.27 h70
  text "3" at 3693.5,2990.7 h60
  text "Top Layer" at 4103.41,2990.7 h60
  text "Copper" at 5033.15,2990.7 h60
  text "1.80mil" at 5892.92,2990.7 h60
  text "L2" at 2965.9,2944.27 h70
  text "4" at 3693.5,2870.7 h60
  text "Dielectric1" at 4103.41,2870.7 h60
  text "FR-4" at 5033.15,2870.7 h60
  text "42.11mil" at 5892.92,2870.7 h60
  text "4.8" at 6542.76,2870.7 h60
  text "5" at 3693.5,2750.7 h60
  text "Bottom Layer" at 4103.41,2750.7 h60
  text "Copper" at 5033.15,2750.7 h60
  text "1.80mil" at 5892.92,2750.7 h60
  text "6" at 3693.5,2630.7 h60
  text "Bottom Solder" at 4103.41,2630.7 h60
  text "Solder Resist" at 5033.15,2630.7 h60
  text "0.60mil" at 5892.92,2630.7 h60
  text "3.5" at 6542.76,2630.7 h60
  text "7" at 3693.5,2510.7 h60
  text "Bottom Overlay" at 4103.41,2510.7 h60
M13 Component Bodies Top:
  lines w6: 150,0 150,350 2150,350
  text ".Layer_Name" at 727,-858.49 h60
M14 Component Bodies Bottom:
  text ".Layer_Name" at 727,-858.49 h60
M15 Courtyards Top:
  text ".Layer_Name" at 727,-858.49 h60
M16 Courtyards Bottom:
  text ".Layer_Name" at 727,-858.49 h60
Drill Drawing:
  lines w10: 1525.69,6782.96 1580.94,6782.96 1553.32,6727.71 1525.69,6782.96 ; 1525.69,6852.03 1580.94,6852.03 1580.94,6907.28 1525.69,6907.28 1525.69,6852.03 ; 1525.69,6990.16 1539.5,6990.16 1553.32,6976.35 1567.13,6990.16 1580.94,6990.16 1567.13,7003.98 1580.94,7017.79 1567.13,7017.79 1553.32,7031.6 1539.5,7017.79 1525.69,7017.79 1539.5,7003.98 1525.69,6990.16
  lines w12: 1475.6,5695.85 4707.09,5695.85 ; 1475.6,7436.33 4707.09,7436.33 ; 1813.46,5571.53 1813.46,7560.65 ; 2145.46,5571.53 2145.46,7560.65 ; 2782.03,5571.53 2782.03,7560.65 ; 3041.17,5571.53 3041.17,7560.65 ; 3416.32,5571.53 3416.32,7560.65 ; 4140.65,5571.53 4140.65,7560.65 ; 1475.6,5571.53 4707.09,5571.53 4707.09,7560.65 1475.6,7560.65 1475.6,5571.53
  text "Symbol" at 1550.19,7473.63 h72
  text "Quantity" at 1850.76,7473.63 h72
  text "Finished Hole Size" at 2182.76,7473.63 h72
  text "Plated" at 2819.32,7473.63 h72
  text "Hole Type" at 3078.46,7473.63 h72
  text "Drill Layer Pair" at 3453.62,7473.63 h72
  text "Hole Tolerance" at 4177.95,7473.63 h72
  text "3" at 1850.76,7349.31 h60
  text "39.00mil (0.991mm)" at 2182.76,7349.31 h60
  text "NPTH" at 2819.32,7349.31 h60
  text "Round" at 3078.46,7349.31 h60
  text "Top Layer - Bottom Layer" at 3453.62,7349.31 h60
  text "D" at 1524.91,7339.32 h55.25
  text "2" at 1850.76,7224.99 h60
  text "39.37mil (1.000mm)" at 2182.76,7224.99 h60
  text "NPTH" at 2819.32,7224.99 h60
  text "Round" at 3078.46,7224.99 h60
  text "Top Layer - Bottom Layer" at 3453.62,7224.99 h60
  text "G" at 1524.91,7215 h55.25
  text "280" at 1850.76,7100.67 h60
  text "7.87mil (0.200mm)" at 2182.76,7100.67 h60
  text "PTH" at 2819.32,7100.67 h60
  text "Round" at 3078.46,7100.67 h60
  text "Top Layer - Bottom Layer" at 3453.62,7100.67 h60
  text "S" at 1524.91,7090.68 h55.25
  text "6" at 1850.76,6976.35 h60
  text "10.00mil (0.254mm)" at 2182.76,6976.35 h60
  text "PTH" at 2819.32,6976.35 h60
  text "Round" at 3078.46,6976.35 h60
  text "Top Layer - Bottom Layer" at 3453.62,6976.35 h60
  text "19" at 1850.76,6852.03 h60
  text "20.00mil (0.508mm)" at 2182.76,6852.03 h60
  text "PTH" at 2819.32,6852.03 h60
  text "Round" at 3078.46,6852.03 h60
  text "Top Layer - Bottom Layer" at 3453.62,6852.03 h60
  text "6" at 1850.76,6727.71 h60
  text "27.56mil (0.700mm)" at 2182.76,6727.71 h60
  text "PTH" at 2819.32,6727.71 h60
  text "Round" at 3078.46,6727.71 h60
  text "Top Layer - Bottom Layer" at 3453.62,6727.71 h60
  text "2" at 1850.76,6603.39 h60
  text "33.47mil (0.850mm)" at 2182.76,6603.39 h60
  text "PTH" at 2819.32,6603.39 h60
  text "Round" at 3078.46,6603.39 h60
  text "Top Layer - Bottom Layer" at 3453.62,6603.39 h60
  text "M" at 1524.91,6593.4 h55.25
  text "4" at 1850.76,6479.07 h60
  text "39.37mil (1.000mm)" at 2182.76,6479.07 h60
  text "PTH" at 2819.32,6479.07 h60
  text "Round" at 3078.46,6479.07 h60
  text "Top Layer - Bottom Layer" at 3453.62,6479.07 h60
  text "E" at 1524.91,6469.08 h55.25
  text "3" at 1850.76,6354.75 h60
  text "40.00mil (1.016mm)" at 2182.76,6354.75 h60
  text "PTH" at 2819.32,6354.75 h60
  text "Round" at 3078.46,6354.75 h60
  text "Top Layer - Bottom Layer" at 3453.62,6354.75 h60
  text "A" at 1524.91,6344.76 h55.25
  text "4" at 1850.76,6230.43 h60
  text "40.16mil (1.020mm)" at 2182.76,6230.43 h60
  text "PTH" at 2819.32,6230.43 h60
  text "Round" at 3078.46,6230.43 h60
  text "Top Layer - Bottom Layer" at 3453.62,6230.43 h60
  text "J" at 1524.91,6220.44 h55.25
  text "2" at 1850.76,6106.11 h60
  text "43.31mil (1.100mm)" at 2182.76,6106.11 h60
  text "PTH" at 2819.32,6106.11 h60
  text "Round" at 3078.46,6106.11 h60
  text "Top Layer - Bottom Layer" at 3453.62,6106.11 h60
  text "R" at 1524.91,6096.12 h55.25
  text "40" at 1850.76,5981.79 h60
  text "45.28mil (1.150mm)" at 2182.76,5981.79 h60
  text "PTH" at 2819.32,5981.79 h60
  text "Round" at 3078.46,5981.79 h60
  text "Top Layer - Bottom Layer" at 3453.62,5981.79 h60
  text "K" at 1524.91,5971.8 h55.25
  text "4" at 1850.76,5857.47 h60
  text "51.18mil (1.300mm)" at 2182.76,5857.47 h60
  text "PTH" at 2819.32,5857.47 h60
  text "Round" at 3078.46,5857.47 h60
  text "Top Layer - Bottom Layer" at 3453.62,5857.47 h60
  text "F" at 1524.91,5847.48 h55.25
  text "2" at 1850.76,5733.15 h60
  text "23.62mil (0.600mm)" at 2182.76,5733.15 h60
  text "PTH" at 2819.32,5733.15 h60
  text "Slot" at 3078.46,5733.15 h60
  text "Top Layer - Bottom Layer" at 3453.62,5733.15 h60
  text "L" at 1524.91,5723.16 h55.25
  text "377 Total" at 1850.76,5608.83 h60
  text "Slot definitions :" at 1550.19,5521.81 h60
  text "Routed Path Length" at 2000.91,5521.81 h60
  text "= Calculated from tool start centre position to tool end centre position." at 2540.64,5521.81 h60
  text "Hole Length" at 2000.91,5472.08 h60
  text "= Routed Path Length + Tool Size = Slot length as defined in the PCB layout" at 2340.84,5472.08 h60
  text "ADDITIONAL FAB NOTES" at 3884.9,1220.6 h100
  text "ALL OTHER DRILL TOLERANCE FOR PLATED +/-3 MIL AND NPTH +/-2 MIL" at 3900.93,747.86 h100
  text "(UNLESS OTHERWISE SPECIFIED)" at 4029.49,495.06 h100
  text "FAB" at 727,-858.49 h60
Mechanical 18:
  lines w3.94: 653.6,525.7 664.6,514.7 906.9,514.7 1013.7,621.5 1013.7,1207 983.6,1237.1 666.7,1237.1 653.6,1224 653.6,525.7
Mechanical 32:
  lines w1: 125,0 175,0 ; 150,-25 150,25

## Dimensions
150,-400 to 1150,-400 on M2 Board Dimensions
0,40 to 2300,40 on M2 Board Dimensions
2260,0 to 2260,1700 on M2 Board Dimensions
